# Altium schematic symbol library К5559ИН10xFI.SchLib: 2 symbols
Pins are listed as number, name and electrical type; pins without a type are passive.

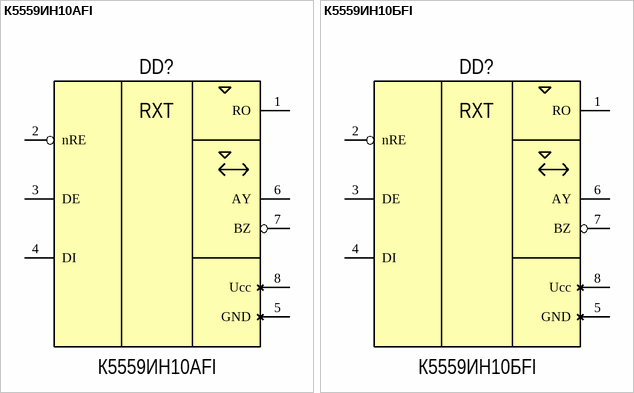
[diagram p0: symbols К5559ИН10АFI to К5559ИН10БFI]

## К5559ИН10АFI
designator DD?
Микросхема приемопередатчика по стандарту RS-485/422
pins: 1 RO, 2 nRE, 3 DE, 4 DI, 5 GND, 6 AY, 7 BZ, 8 Ucc

## К5559ИН10БFI
designator DD?
Микросхема приемопередатчика по стандарту RS-485/422
pins: 1 RO, 2 nRE, 3 DE, 4 DI, 5 GND, 6 AY, 7 BZ, 8 Ucc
